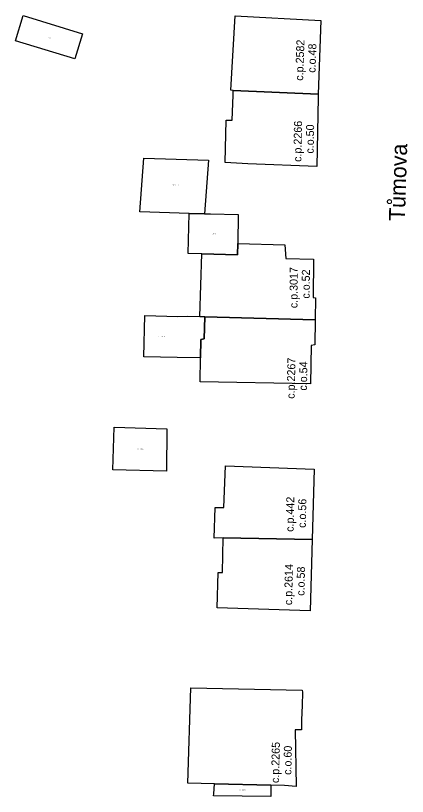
# Model space of a CAD drawing. Extents: x -600391 to -599491, y -1160176 to -1159402.
# Drawn here: x -599944.2 to -599895.2, y -1159645.2 to -1159547.6 of the extents above; entities that cross this region are included whole.
import ezdxf

# ---------------------------------------------------------------- set-up
doc = ezdxf.new("R2010")
doc.units = 0
for name, color, linetype in [('Level 10', 7, 'Continuous'), ('Level 11', 7, 'Continuous'), ('Level 12', 7, 'Continuous'), ('Level 24', 7, 'Continuous'), ('Level 25', 7, 'Continuous'), ('Level 61', 7, 'Continuous'), ('Level 62', 7, 'Continuous')]:
    doc.layers.add(name, color=color, linetype=linetype)

msp = doc.modelspace()

# ---------------------------------------------------------------- linework, layer by layer
at = {"layer": 'Level 61'}
for points in [[(-599944.17, -1159550.78), (-599943.22, -1159547.65)], [(-599943.22, -1159547.65), (-599935.81, -1159549.93)], [(-599917.3, -1159556.97), (-599916.77, -1159547.68)], [(-599916.77, -1159547.68), (-599906.07, -1159548.24)], [(-599906.07, -1159548.24), (-599906.4, -1159557.47)], [(-599935.81, -1159549.93), (-599936.76, -1159553.06)], [(-599936.76, -1159553.06), (-599944.17, -1159550.78)], [(-599917, -1159556.99), (-599917.3, -1159556.97)], [(-599906.4, -1159557.47), (-599917, -1159556.99)], [(-599916.99, -1159557.61), (-599917, -1159556.99)], [(-599917, -1159556.99), (-599906.4, -1159557.47)], [(-599917.11, -1159560.73), (-599916.99, -1159557.61)], [(-599906.4, -1159557.89), (-599906.56, -1159566.52)], [(-599906.4, -1159557.47), (-599906.4, -1159557.89)], [(-599918.02, -1159566), (-599917.89, -1159560.71)], [(-599917.89, -1159560.71), (-599917.11, -1159560.73)], [(-599928.65, -1159572.17), (-599928.14, -1159565.47)], [(-599928.14, -1159565.47), (-599920.08, -1159565.73)], [(-599920.08, -1159565.73), (-599920.57, -1159572.41)], [(-599915.18, -1159566.17), (-599918.02, -1159566)], [(-599906.56, -1159566.52), (-599915.18, -1159566.17)], [(-599922.5, -1159572.37), (-599928.65, -1159572.17)], [(-599922.64, -1159577.38), (-599922.5, -1159572.37)], [(-599922.5, -1159572.37), (-599920.57, -1159572.41)], [(-599920.57, -1159572.41), (-599922.5, -1159572.37)], [(-599920.57, -1159572.41), (-599919.84, -1159572.43)], [(-599919.84, -1159572.43), (-599919.83, -1159572.43)], [(-599919.83, -1159572.43), (-599916.38, -1159572.51)], [(-599916.38, -1159572.51), (-599916.43, -1159576.13)], [(-599916.43, -1159576.13), (-599916.47, -1159577.55)], [(-599916.47, -1159577.55), (-599916.43, -1159576.13)], [(-599916.43, -1159576.13), (-599910.53, -1159576.3)], [(-599910.53, -1159576.3), (-599910.43, -1159577.99)], [(-599920.93, -1159577.42), (-599922.64, -1159577.38)], [(-599921.15, -1159585.25), (-599920.93, -1159577.42)], [(-599916.47, -1159577.55), (-599920.93, -1159577.42)], [(-599920.93, -1159577.42), (-599916.47, -1159577.55)], [(-599910.43, -1159577.99), (-599906.98, -1159578.08)], [(-599906.98, -1159578.08), (-599907.02, -1159582.85)], [(-599907.02, -1159582.85), (-599906.73, -1159582.9)], [(-599906.73, -1159582.9), (-599906.76, -1159585.66)], [(-599928.14, -1159590.29), (-599928.03, -1159585.11)], [(-599928.03, -1159585.11), (-599923.92, -1159585.25)], [(-599923.92, -1159585.25), (-599922.7, -1159585.22)], [(-599922.7, -1159585.22), (-599921.15, -1159585.25)], [(-599921.15, -1159585.25), (-599920.53, -1159585.29)], [(-599920.53, -1159585.29), (-599921.15, -1159585.25)], [(-599920.53, -1159585.29), (-599920.63, -1159588.05)], [(-599920.63, -1159588.05), (-599920.53, -1159585.29)], [(-599906.76, -1159585.66), (-599920.53, -1159585.29)], [(-599920.53, -1159585.29), (-599906.76, -1159585.66)], [(-599906.76, -1159585.66), (-599906.81, -1159588.78)], [(-599921.06, -1159588.11), (-599921.1, -1159590.4)], [(-599921.1, -1159590.4), (-599921.06, -1159588.11)], [(-599920.63, -1159588.05), (-599921.06, -1159588.11)], [(-599921.06, -1159588.11), (-599920.63, -1159588.05)], [(-599907.25, -1159588.85), (-599907.36, -1159593.65)], [(-599906.81, -1159588.78), (-599907.25, -1159588.85)], [(-599923.98, -1159590.37), (-599928.14, -1159590.29)], [(-599921.1, -1159590.4), (-599923.98, -1159590.37)], [(-599921.14, -1159593.42), (-599921.1, -1159590.4)], [(-599907.36, -1159593.65), (-599921.14, -1159593.42)], [(-599932.01, -1159604.39), (-599931.86, -1159599.07)], [(-599931.86, -1159599.07), (-599925.28, -1159599.27)], [(-599925.28, -1159599.27), (-599925.32, -1159604.55)], [(-599918.17, -1159609.1), (-599917.96, -1159603.9)], [(-599917.96, -1159603.9), (-599906.88, -1159604.3)], [(-599925.32, -1159604.55), (-599932.01, -1159604.39)], [(-599906.88, -1159604.3), (-599907.12, -1159613.12)], [(-599919.38, -1159612.92), (-599919.26, -1159609.1)], [(-599919.26, -1159609.1), (-599918.17, -1159609.1)], [(-599918.24, -1159612.9), (-599919.38, -1159612.92)], [(-599918.34, -1159617.21), (-599918.24, -1159612.9)], [(-599918.24, -1159612.9), (-599907.12, -1159613.12)], [(-599907.12, -1159613.12), (-599918.24, -1159612.9)], [(-599907.12, -1159613.12), (-599907.39, -1159622.03)], [(-599919, -1159621.63), (-599918.87, -1159617.24)], [(-599918.87, -1159617.24), (-599918.34, -1159617.21)], [(-599907.39, -1159622.03), (-599919, -1159621.63)], [(-599922.65, -1159643.53), (-599922.3, -1159631.62)], [(-599922.3, -1159631.62), (-599908.38, -1159631.94)], [(-599908.34, -1159632.16), (-599908.4, -1159633.84)], [(-599908.38, -1159631.94), (-599908.34, -1159632.16)], [(-599908.4, -1159633.84), (-599908.45, -1159635.63)], [(-599908.45, -1159635.63), (-599908.48, -1159636.88)], [(-599908.48, -1159636.88), (-599909.25, -1159636.9)], [(-599909.25, -1159636.9), (-599909.13, -1159643.97)], [(-599919.35, -1159643.64), (-599922.65, -1159643.53)], [(-599919.42, -1159644.87), (-599919.35, -1159643.64)], [(-599919.35, -1159643.64), (-599912.28, -1159643.8)], [(-599912.28, -1159643.8), (-599919.35, -1159643.64)], [(-599912.28, -1159643.8), (-599912.31, -1159644.91)], [(-599910.61, -1159643.83), (-599912.28, -1159643.8)], [(-599909.13, -1159643.97), (-599910.61, -1159643.83)], [(-599919.44, -1159645.14), (-599919.42, -1159644.87)], [(-599912.31, -1159644.91), (-599912.3, -1159645.2)], [(-599912.3, -1159645.2), (-599919.44, -1159645.14)]]:
    msp.add_lwpolyline(points, dxfattribs=at)
at = {"layer": 'Level 62'}
for points in [[(-599943.22, -1159547.65), (-599935.81, -1159549.93), (-599936.76, -1159553.06), (-599944.17, -1159550.78), (-599943.22, -1159547.65)], [(-599906.07, -1159548.24), (-599906.4, -1159557.47), (-599917, -1159556.99), (-599917.3, -1159556.97), (-599916.77, -1159547.68), (-599906.07, -1159548.24)], [(-599918.02, -1159566), (-599917.89, -1159560.71), (-599917.11, -1159560.73), (-599916.99, -1159557.61), (-599917, -1159556.99), (-599906.4, -1159557.47), (-599906.4, -1159557.89), (-599906.56, -1159566.52), (-599915.18, -1159566.17), (-599918.02, -1159566)], [(-599922.5, -1159572.37), (-599928.65, -1159572.17), (-599928.14, -1159565.47), (-599920.08, -1159565.73), (-599920.57, -1159572.41), (-599922.5, -1159572.37)], [(-599922.5, -1159572.37), (-599920.57, -1159572.41), (-599919.84, -1159572.43), (-599919.83, -1159572.43), (-599916.38, -1159572.51), (-599916.43, -1159576.13), (-599916.47, -1159577.55), (-599920.93, -1159577.42), (-599922.64, -1159577.38), (-599922.5, -1159572.37)], [(-599920.93, -1159577.42), (-599916.47, -1159577.55), (-599916.43, -1159576.13), (-599910.53, -1159576.3), (-599910.43, -1159577.99), (-599906.98, -1159578.08), (-599907.02, -1159582.85), (-599906.73, -1159582.9), (-599906.76, -1159585.66), (-599920.53, -1159585.29), (-599921.15, -1159585.25), (-599920.93, -1159577.42)], [(-599921.1, -1159590.4), (-599923.98, -1159590.37), (-599928.14, -1159590.29), (-599928.03, -1159585.11), (-599923.92, -1159585.25), (-599922.7, -1159585.22), (-599921.15, -1159585.25), (-599920.53, -1159585.29), (-599920.63, -1159588.05), (-599921.06, -1159588.11), (-599921.1, -1159590.4)], [(-599921.1, -1159590.4), (-599921.06, -1159588.11), (-599920.63, -1159588.05), (-599920.53, -1159585.29), (-599906.76, -1159585.66), (-599906.81, -1159588.78), (-599907.25, -1159588.85), (-599907.36, -1159593.65), (-599921.14, -1159593.42), (-599921.1, -1159590.4)], [(-599931.86, -1159599.07), (-599925.28, -1159599.27), (-599925.32, -1159604.55), (-599932.01, -1159604.39), (-599931.86, -1159599.07)], [(-599917.96, -1159603.9), (-599906.88, -1159604.3), (-599907.12, -1159613.12), (-599918.24, -1159612.9), (-599919.38, -1159612.92), (-599919.26, -1159609.1), (-599918.17, -1159609.1), (-599917.96, -1159603.9)], [(-599918.24, -1159612.9), (-599907.12, -1159613.12), (-599907.39, -1159622.03), (-599919, -1159621.63), (-599918.87, -1159617.24), (-599918.34, -1159617.21), (-599918.24, -1159612.9)], [(-599908.34, -1159632.16), (-599908.4, -1159633.84), (-599908.45, -1159635.63), (-599908.48, -1159636.88), (-599909.25, -1159636.9), (-599909.13, -1159643.97), (-599910.61, -1159643.83), (-599912.28, -1159643.8), (-599919.35, -1159643.64), (-599922.65, -1159643.53), (-599922.3, -1159631.62), (-599908.38, -1159631.94), (-599908.34, -1159632.16)], [(-599912.28, -1159643.8), (-599912.31, -1159644.91), (-599912.3, -1159645.2), (-599919.44, -1159645.14), (-599919.42, -1159644.87), (-599919.35, -1159643.64), (-599912.28, -1159643.8)]]:
    msp.add_lwpolyline(points, dxfattribs=at)

# ---------------------------------------------------------------- texts
at = {"layer": 'Level 10'}
for s, rotation, p in [('c.o.48', 87.95418, (-599906.727, -1159554.802)), ('c.o.50', 88.98577, (-599906.954, -1159564.897)), ('c.o.52', 89.51873, (-599907.449, -1159583.012)), ('c.o.54', 88.68776, (-599907.798, -1159594.511)), ('c.o.56', 88.68776, (-599907.937, -1159611.663)), ('c.o.58', 88.68776, (-599908.108, -1159620.141)), ('c.o.60', 88.68776, (-599909.746, -1159642.52))]:
    msp.add_text(s, height=1, rotation=rotation, dxfattribs=at).set_placement(p)
at = {"layer": 'Level 11'}
msp.add_text('Tůmova', height=2, rotation=88.19467, dxfattribs=at).set_placement((-599895.561, -1159573.331))
at = {"layer": 'Level 12'}
for s, rotation, p in [('c.p.2582', 87.95418, (-599908.273, -1159555.797)), ('c.p.2266', 88.98577, (-599908.488, -1159565.931)), ('c.p.3017', 89.51873, (-599908.972, -1159584.205)), ('c.p.2267', 88.68776, (-599909.331, -1159595.528)), ('c.p.442', 88.68776, (-599909.46, -1159612.154)), ('c.p.2614', 88.68776, (-599909.648, -1159621.312)), ('c.p.2265', 88.68776, (-599911.281, -1159643.538))]:
    msp.add_text(s, height=1, rotation=rotation, dxfattribs=at).set_placement(p)
at = {"layer": 'Level 24'}
msp.add_text('c.z.2103', height=0.1, dxfattribs=at).set_placement((-599919.744, -1159574.967))
at = {"layer": 'Level 25'}
for s, p in [('c.pp.1305_A', (-599940.507, -1159550.446)), ('c.pp.2266_A', (-599924.608, -1159568.867)), ('c.pp.2267_A', (-599926.338, -1159587.777)), ('c.pp.442_A', (-599928.923, -1159601.837)), ('c.pp.2265_A', (-599916.188, -1159644.437))]:
    msp.add_text(s, height=0.1, dxfattribs=at).set_placement(p)

doc.saveas('drawing.dxf')
